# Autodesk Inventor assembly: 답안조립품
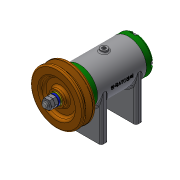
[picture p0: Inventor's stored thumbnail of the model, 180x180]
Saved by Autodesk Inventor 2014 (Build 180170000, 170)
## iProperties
Created: 2020-07
Part Number: 답안조립품
Document SubType Name: Assembly
Designer: kh
Author: kh
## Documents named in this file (15)
- C:\Users\kh\Desktop\700706V1019\답안조립품.iam
- C:\Users\kh\Desktop\700706V1019\본체.ipt
- C:\Users\kh\Desktop\700706V1019\베어링 6002.ipt
- C:\Users\kh\Desktop\700706V1019\앞커버.ipt
- C:\Users\kh\Desktop\700706V1019\뒤커버.ipt
- C:\Users\kh\Desktop\700706V1019\오일 실 15 25 7.ipt
- C:\Users\kh\Desktop\700706V1019\축.ipt
- C:\Users\kh\Desktop\700706V1019\키 3x3x12.ipt
- C:\Users\kh\Desktop\700706V1019\V벨트풀리.ipt
- C:\Users\kh\Desktop\700706V1019\와셔 8x17.ipt
- C:\Users\kh\Desktop\700706V1019\스프링와셔 8.ipt
- C:\Users\kh\Desktop\700706V1019\너트 M8.ipt
- C:\Users\kh\Desktop\700706V1019\와셔 6x11.5.ipt
- C:\Users\kh\Desktop\700706V1019\볼트 M6x8.ipt
- C:\Users\kh\Desktop\700706V1019\볼트 M4x12.ipt
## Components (1 placed, 1 different names)
1. V벨트풀리:1 — Mate:18, Mate:19, Mate:20, Mate:22
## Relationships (4: Mate 4)
- Mate:18: V벨트풀리:1
- Mate:19: V벨트풀리:1
- Mate:20: V벨트풀리:1
- Mate:22: V벨트풀리:1
